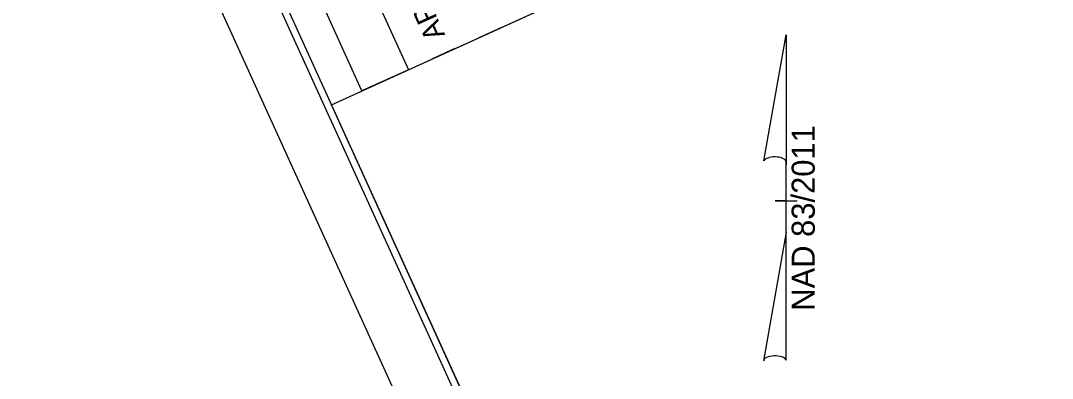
# Model space of a CAD drawing. Extents: x 2097307 to 2099001, y 683921 to 685907.
# Drawn here: x 2097306.7 to 2097686.2, y 685156.2 to 685287.8 of the extents above; entities that cross this region are included whole.
import ezdxf

# ---------------------------------------------------------------- set-up
doc = ezdxf.new("R2010")
doc.units = 0
for name, color, linetype in [('Default', 7, 'Continuous'), ('Sheet Data Field CELL', 7, 'Continuous'), ('Sheet Layout Plan Border', 7, 'Continuous'), ('Sheet Plan CELL', 7, 'Continuous'), ('Sheet Plot Border Inside CELL', 7, 'Continuous'), ('Sheet Plot Border Outside CELL', 7, 'Continuous'), ('Sheet Title CELL', 7, 'Continuous')]:
    doc.layers.add(name, color=color, linetype=linetype)

msp = doc.modelspace()

# ---------------------------------------------------------------- linework, layer by layer
at = {"layer": 'Default'}
for p, q in [((2097580.05, 685236.17), (2097588.25, 685282.52)), ((2097588.3, 685282.52), (2097588.25, 685282.52)), ((2097588.3, 685282.52), (2097588.25, 685282.52)), ((2097588.3, 685282.52), (2097588.3, 685234.72)), ((2097588.3, 685209.92), (2097588.3, 685236.12)), ((2097588.3, 685234.72), (2097588.3, 685236.07)), ((2097584.3, 685221.52), (2097584.25, 685221.52)), ((2097587.85, 685221.52), (2097584.3, 685221.52)), ((2097584.35, 685221.52), (2097592.35, 685221.52)), ((2097588.3, 685209.92), (2097579.95, 685162.67)), ((2097588.35, 685162.87), (2097588.3, 685209.92))]:
    msp.add_line(p, q, dxfattribs=at)
for centre, start_param, end_param in [((2097584.19, 685235.67), 0.216388, 2.908219), ((2097584.19, 685162.5), 0.201328, 3.141593)]:
    msp.add_ellipse(centre, major_axis=(4.23, -0.03), ratio=0.461098, start_param=start_param, end_param=end_param, dxfattribs=at)
at = {"layer": 'Sheet Layout Plan Border'}
msp.add_lwpolyline([(2098458.66, 685511.51), (2098911.14, 684517.12), (2097955.44, 684082.23), (2097420.98, 685256.77), (2097639.51, 685356.21), (2097584.97, 685476.06), (2098243.4, 685773.28), (2098379.01, 685475.27)], close=True, dxfattribs=at)
at = {"layer": 'Sheet Plan CELL'}
msp.add_line((2097334.17, 685447.53), (2097955.44, 684082.22), dxfattribs=at)
at = {"layer": 'Sheet Plot Border Inside CELL'}
msp.add_lwpolyline([(2098977, 684378.44), (2098287, 685894.78), (2097326.75, 685457.84), (2098016.75, 683941.49)], close=True, dxfattribs=at)
at = {"layer": 'Sheet Plot Border Outside CELL'}
msp.add_lwpolyline([(2099000.59, 684374.9), (2098303.35, 685907.17), (2097306.68, 685453.65), (2098003.93, 683921.37)], close=True, dxfattribs=at)
at = {"layer": 'Sheet Title CELL'}
for p, q in [((2097362.54, 685460.43), (2097449.34, 685269.68)), ((2097432.25, 685261.9), (2097382.42, 685371.41)), ((2097420.98, 685256.77), (2097593.2, 685335.14)), ((2097483.53, 685285.23), (2097474.99, 685281.35)), ((2097466.44, 685277.46), (2097457.9, 685273.57)), ((2097449.34, 685269.68), (2097432.25, 685261.9))]:
    msp.add_line(p, q, dxfattribs=at)

# ---------------------------------------------------------------- texts
at = {"layer": 'Default'}
msp.add_text('NAD 83/2011', height=8.5, rotation=90, dxfattribs=at).set_placement((2097598.82, 685181.05))
at = {"layer": 'Sheet Data Field CELL'}
msp.add_text('APPROVED:', height=7.512, rotation=114.4674, dxfattribs=at).set_placement((2097462.89, 685282.53))

doc.saveas('drawing.dxf')
